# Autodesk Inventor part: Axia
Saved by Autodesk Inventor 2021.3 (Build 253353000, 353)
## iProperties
Created: 2022-09
Part Number: Axia
Material: Generic
Document SubType Name: Modeling
Designer: Administrator
Density: 1 g/cm^3
Appearance: Default
Title: Axia v3
Author: Administrator
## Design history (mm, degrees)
feature "Axia" [Body]
feature "Socket Body" [Body]
feature "Shade Ring" [Body]
feature "Shade Ring +Collar" [Body]
feature "Socket" [Body]
feature "Body1"
feature "Metal Strain Relief" [Body]
feature "Fabric Cord (1)" [Body]
feature "Stem (Threaded)" [Body]
feature "Cap (Threaded)" [Body]
feature "T9-Bulb" [Body]
body "Solid1"
body "Solid2"
body "Solid3"
body "Solid4"
body "Solid5"
body "Solid6"
body "Solid7"
body "Solid8"
body "Solid9"
body "Solid10"
body "Solid11"
